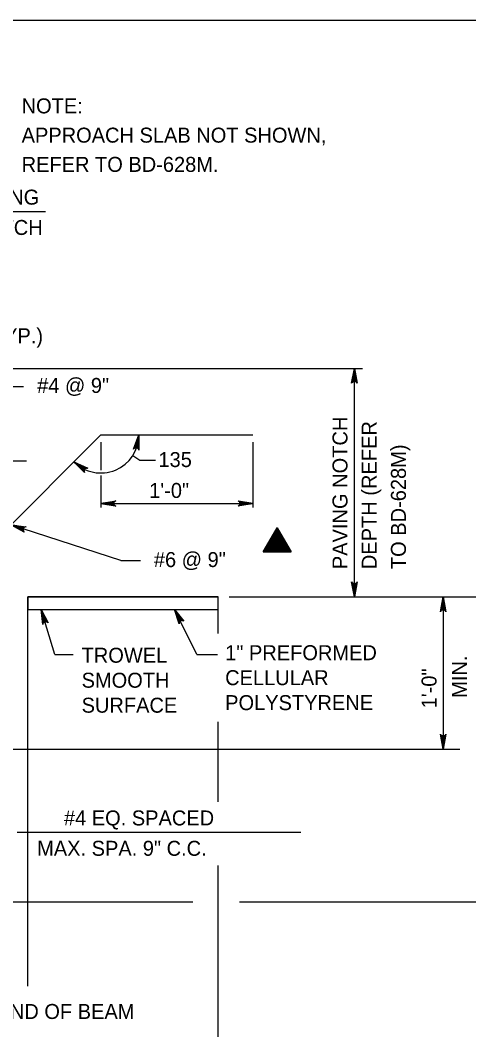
# Model space of a CAD drawing. Extents: x 638653 to 642302, y 298557 to 300414.
# Drawn here: x 640287.7 to 640377.6, y 299527.4 to 299729.5 of the extents above; entities that cross this region are included whole.
import ezdxf

# ---------------------------------------------------------------- set-up
doc = ezdxf.new("R2010")
doc.units = 0
doc.layers.add('1', color=7, linetype='Continuous')

msp = doc.modelspace()

# ---------------------------------------------------------------- linework, layer by layer
at = {"layer": '1'}
for p, q in [((639863.16, 299729.52), (640649.16, 299729.52)), ((640251.13, 299691.25), (640292.75, 299691.25)), ((640275.45, 299659.83), (640356.29, 299659.83)), ((640354.65, 299614.11), (640354.65, 299659.83)), ((640282.86, 299656.2), (640288.33, 299656.2)), ((640240.92, 299583.57), (640303.84, 299646.5)), ((640303.84, 299646.5), (640334.32, 299646.5)), ((640303.84, 299645.08), (640303.84, 299639.47)), ((640334.32, 299645.08), (640334.32, 299631.95)), ((640310.25, 299642.38), (640311.66, 299641.48)), ((640265.67, 299641.32), (640288.96, 299641.32)), ((640311.66, 299641.48), (640314.81, 299641.48)), ((640303.84, 299638.36), (640303.84, 299631.95)), ((640303.84, 299632.78), (640334.32, 299632.78)), ((640307.83, 299621.35), (640285.84, 299628.5)), ((640339.18, 299624.69), (640339.18, 299624.69)), ((640307.83, 299621.35), (640311.8, 299621.35)), ((640289.23, 299536.15), (640289.23, 299614.11)), ((640289.23, 299614.11), (640327.33, 299614.11)), ((640327.33, 299606.73), (640327.33, 299614.11)), ((640329.54, 299614.11), (640386.72, 299614.11)), ((640372.44, 299614.11), (640372.44, 299583.63)), ((640289.23, 299611.57), (640327.33, 299611.57)), ((640294.61, 299602.54), (640291.86, 299611.57)), ((640323.1, 299602.56), (640318.59, 299611.57)), ((640294.61, 299602.54), (640298.3, 299602.54)), ((640323.1, 299602.56), (640327.24, 299602.56)), ((640327.33, 299573.06), (640327.33, 299589.09)), ((640258.7, 299583.63), (640375.77, 299583.63)), ((640287.05, 299566.99), (640343.95, 299566.99)), ((640327.33, 299518.76), (640327.33, 299560.28)), ((640276.15, 299553.07), (640322.31, 299553.07)), ((640331.65, 299553.07), (640386.72, 299553.07))]:
    msp.add_line(p, q, dxfattribs=at)
for points in [[(640354.65, 299659.83), (640355.21, 299656.84), (640355.05, 299657.07), (640354.85, 299657.19), (640354.65, 299657.23), (640354.45, 299657.19), (640354.25, 299657.07), (640354.09, 299656.84), (640354.65, 299659.83), (640354.25, 299657.07), (640354.45, 299657.19), (640354.65, 299659.83), (640354.65, 299657.23), (640354.85, 299657.19), (640354.65, 299659.83), (640355.05, 299657.07)], [(640311.46, 299646.5), (640311.49, 299643.46), (640311.43, 299643.59), (640311.37, 299643.71), (640311.29, 299643.79), (640311.2, 299643.87), (640311.1, 299643.9), (640311.01, 299643.93), (640310.91, 299643.94), (640310.8, 299643.94), (640310.7, 299643.89), (640310.59, 299643.85), (640310.49, 299643.75), (640310.39, 299643.65), (640311.46, 299646.5), (640310.49, 299643.75), (640310.59, 299643.85), (640311.46, 299646.5), (640310.7, 299643.89), (640310.8, 299643.94), (640311.46, 299646.5), (640310.91, 299643.94), (640311.01, 299643.93), (640311.46, 299646.5), (640311.1, 299643.9), (640311.2, 299643.87), (640311.46, 299646.5), (640311.29, 299643.79), (640311.37, 299643.71), (640311.46, 299646.5), (640311.43, 299643.59)], [(640298.45, 299641.11), (640301.22, 299639.87), (640301.08, 299639.87), (640300.94, 299639.87), (640300.84, 299639.82), (640300.73, 299639.78), (640300.66, 299639.7), (640300.59, 299639.63), (640300.55, 299639.54), (640300.5, 299639.45), (640300.5, 299639.33), (640300.49, 299639.21), (640300.54, 299639.08), (640300.59, 299638.95), (640298.45, 299641.11), (640300.54, 299639.08), (640300.49, 299639.21), (640298.45, 299641.11), (640300.5, 299639.33), (640300.5, 299639.45), (640298.45, 299641.11), (640300.55, 299639.54), (640300.59, 299639.63), (640298.45, 299641.11), (640300.66, 299639.7), (640300.73, 299639.78), (640298.45, 299641.11), (640300.84, 299639.82), (640300.94, 299639.87), (640298.45, 299641.11), (640301.08, 299639.87)], [(640303.84, 299632.78), (640306.82, 299633.34), (640306.71, 299633.26), (640306.59, 299633.18), (640306.53, 299633.08), (640306.47, 299632.98), (640306.46, 299632.88), (640306.44, 299632.78), (640306.46, 299632.68), (640306.47, 299632.58), (640306.53, 299632.48), (640306.59, 299632.38), (640306.71, 299632.3), (640306.82, 299632.23), (640303.84, 299632.78), (640306.71, 299632.3), (640306.59, 299632.38), (640303.84, 299632.78), (640306.53, 299632.48), (640306.47, 299632.58), (640303.84, 299632.78), (640306.46, 299632.68), (640306.44, 299632.78), (640303.84, 299632.78), (640306.46, 299632.88), (640306.47, 299632.98), (640303.84, 299632.78), (640306.53, 299633.08), (640306.59, 299633.18), (640303.84, 299632.78), (640306.71, 299633.26)], [(640334.32, 299632.78), (640331.34, 299632.23), (640331.45, 299632.3), (640331.57, 299632.38), (640331.62, 299632.48), (640331.68, 299632.58), (640331.7, 299632.68), (640331.72, 299632.78), (640331.7, 299632.88), (640331.68, 299632.98), (640331.62, 299633.08), (640331.57, 299633.18), (640331.45, 299633.26), (640331.34, 299633.34), (640334.32, 299632.78), (640331.45, 299633.26), (640331.57, 299633.18), (640334.32, 299632.78), (640331.62, 299633.08), (640331.68, 299632.98), (640334.32, 299632.78), (640331.7, 299632.88), (640331.72, 299632.78), (640334.32, 299632.78), (640331.7, 299632.68), (640331.68, 299632.58), (640334.32, 299632.78), (640331.62, 299632.48), (640331.57, 299632.38), (640334.32, 299632.78), (640331.45, 299632.3)], [(640285.84, 299628.5), (640288.85, 299628.13), (640288.72, 299628.08), (640288.58, 299628.04), (640288.5, 299627.97), (640288.41, 299627.89), (640288.36, 299627.8), (640288.32, 299627.71), (640288.3, 299627.61), (640288.29, 299627.51), (640288.32, 299627.39), (640288.34, 299627.28), (640288.43, 299627.17), (640288.51, 299627.06), (640285.84, 299628.5), (640288.43, 299627.17), (640288.34, 299627.28), (640285.84, 299628.5), (640288.32, 299627.39), (640288.29, 299627.51), (640285.84, 299628.5), (640288.3, 299627.61), (640288.32, 299627.71), (640285.84, 299628.5), (640288.36, 299627.8), (640288.41, 299627.89), (640285.84, 299628.5), (640288.5, 299627.97), (640288.58, 299628.04), (640285.84, 299628.5), (640288.72, 299628.08)], [(640336.39, 299623.08), (640341.97, 299623.08), (640339.18, 299627.91), (640336.39, 299623.08)], [(640336.39, 299623.08), (640339.18, 299627.91), (640341.97, 299623.08), (640336.39, 299623.08), (640339.17, 299627.77), (640341.88, 299623.15), (640336.5, 299623.14), (640339.18, 299627.63), (640341.76, 299623.22), (640336.63, 299623.2), (640339.19, 299627.48), (640341.64, 299623.31), (640336.75, 299623.27), (640339.18, 299627.34), (640341.52, 299623.37), (640336.88, 299623.36), (640339.19, 299627.17), (640341.38, 299623.44), (640337.03, 299623.44), (640339.18, 299627), (640341.25, 299623.52), (640337.16, 299623.51), (640339.17, 299626.83), (640341.11, 299623.61), (640337.3, 299623.59), (640339.17, 299626.67), (640340.96, 299623.69), (640337.43, 299623.67), (640339.19, 299626.52), (640340.79, 299623.77), (640337.57, 299623.75), (640339.19, 299626.35), (640340.62, 299623.88), (640337.72, 299623.83), (640339.19, 299626.17), (640340.48, 299623.98), (640337.87, 299623.91), (640339.19, 299626), (640340.33, 299624.06), (640338.04, 299623.99), (640339.19, 299625.84), (640340.19, 299624.14), (640338.2, 299624.07), (640339.19, 299625.66), (640340.03, 299624.23), (640338.37, 299624.16), (640339.19, 299625.5), (640339.86, 299624.32), (640338.5, 299624.24), (640339.18, 299625.33), (640339.71, 299624.41), (640338.66, 299624.31), (640339.18, 299625.18), (640339.57, 299624.46), (640338.79, 299624.39), (640339.18, 299625.02), (640339.45, 299624.54), (640338.92, 299624.46), (640339.19, 299624.86), (640339.34, 299624.6), (640339.07, 299624.56), (640339.18, 299624.69), (640341.95, 299623.1), (640339.18, 299624.69), (640339.18, 299627.88), (640339.19, 299624.68), (640336.4, 299623.09)], [(640354.65, 299614.11), (640354.09, 299617.09), (640354.25, 299616.86), (640354.45, 299616.74), (640354.65, 299616.71), (640354.85, 299616.74), (640355.05, 299616.86), (640355.21, 299617.09), (640354.65, 299614.11), (640355.05, 299616.86), (640354.85, 299616.74), (640354.65, 299614.11), (640354.65, 299616.71), (640354.45, 299616.74), (640354.65, 299614.11), (640354.25, 299616.86)], [(640372.44, 299614.11), (640373, 299611.12), (640372.92, 299611.24), (640372.84, 299611.35), (640372.74, 299611.41), (640372.64, 299611.47), (640372.54, 299611.49), (640372.44, 299611.51), (640372.34, 299611.49), (640372.24, 299611.47), (640372.14, 299611.41), (640372.04, 299611.35), (640371.96, 299611.24), (640371.88, 299611.12), (640372.44, 299614.11), (640371.96, 299611.24), (640372.04, 299611.35), (640372.44, 299614.11), (640372.14, 299611.41), (640372.24, 299611.47), (640372.44, 299614.11), (640372.34, 299611.49), (640372.44, 299611.51), (640372.44, 299614.11), (640372.54, 299611.49), (640372.64, 299611.47), (640372.44, 299614.11), (640372.74, 299611.41), (640372.84, 299611.35), (640372.44, 299614.11), (640372.92, 299611.24)], [(640291.86, 299611.57), (640293.26, 299608.88), (640293.15, 299608.96), (640293.04, 299609.05), (640292.93, 299609.08), (640292.82, 299609.11), (640292.72, 299609.09), (640292.62, 299609.08), (640292.53, 299609.04), (640292.44, 299608.99), (640292.36, 299608.9), (640292.28, 299608.82), (640292.24, 299608.69), (640292.19, 299608.55), (640291.86, 299611.57), (640292.24, 299608.69), (640292.28, 299608.82), (640291.86, 299611.57), (640292.36, 299608.9), (640292.44, 299608.99), (640291.86, 299611.57), (640292.53, 299609.04), (640292.62, 299609.08), (640291.86, 299611.57), (640292.72, 299609.09), (640292.82, 299609.11), (640291.86, 299611.57), (640292.93, 299609.08), (640293.04, 299609.05), (640291.86, 299611.57), (640293.15, 299608.96)], [(640318.59, 299611.57), (640320.5, 299609.21), (640320.37, 299609.27), (640320.25, 299609.34), (640320.13, 299609.34), (640320.02, 299609.34), (640319.92, 299609.31), (640319.82, 299609.28), (640319.74, 299609.22), (640319.66, 299609.15), (640319.6, 299609.06), (640319.54, 299608.96), (640319.53, 299608.82), (640319.51, 299608.68), (640318.59, 299611.57), (640319.53, 299608.82), (640319.54, 299608.96), (640318.59, 299611.57), (640319.6, 299609.06), (640319.66, 299609.15), (640318.59, 299611.57), (640319.74, 299609.22), (640319.82, 299609.28), (640318.59, 299611.57), (640319.92, 299609.31), (640320.02, 299609.34), (640318.59, 299611.57), (640320.13, 299609.34), (640320.25, 299609.34), (640318.59, 299611.57), (640320.37, 299609.27)], [(640372.44, 299583.63), (640371.88, 299586.61), (640371.96, 299586.49), (640372.04, 299586.38), (640372.14, 299586.32), (640372.24, 299586.26), (640372.34, 299586.24), (640372.44, 299586.23), (640372.54, 299586.24), (640372.64, 299586.26), (640372.74, 299586.32), (640372.84, 299586.38), (640372.92, 299586.49), (640373, 299586.61), (640372.44, 299583.63), (640372.92, 299586.49), (640372.84, 299586.38), (640372.44, 299583.63), (640372.74, 299586.32), (640372.64, 299586.26), (640372.44, 299583.63), (640372.54, 299586.24), (640372.44, 299586.23), (640372.44, 299583.63), (640372.34, 299586.24), (640372.24, 299586.26), (640372.44, 299583.63), (640372.14, 299586.32), (640372.04, 299586.38), (640372.44, 299583.63), (640371.96, 299586.49)]]:
    msp.add_lwpolyline(points, dxfattribs=at)
msp.add_lwpolyline([(640289.23, 299611.57), (640327.33, 299611.57), (640327.33, 299614.11), (640289.23, 299614.11)], close=True, dxfattribs=at)
msp.add_arc((640303.84, 299646.5), 7.62, 225, 0, dxfattribs=at)

# ---------------------------------------------------------------- texts
for s, p in [('NOTE:', (640287.97, 299710.87)), ('APPROACH SLAB NOT SHOWN,', (640287.97, 299705.01)), ('REFER TO BD-628M.', (640287.97, 299699.16)), ('PAVING', (640276.35, 299692.6)), ('NOTCH', (640277.93, 299686.53)), ('TO SKEW (TYP.)', (640261.06, 299664.85)), ('#4 @ 9"', (640291.08, 299654.91)), ('135', (640315.39, 299640.07)), ('1\'-0"', (640313.54, 299633.89)), ('#6 @ 9"', (640314.47, 299620.05)), ('TROWEL', (640299.99, 299600.9)), ('1" PREFORMED', (640328.76, 299601.41)), ('SMOOTH', (640299.99, 299595.9)), ('CELLULAR', (640328.76, 299596.41)), ('SURFACE', (640299.99, 299590.9)), ('POLYSTYRENE', (640328.76, 299591.41)), ('#4 EQ. SPACED', (640296.45, 299568.33)), ('MAX. SPA. 9" C.C.', (640291.08, 299562.25)), ('END OF BEAM', (640282.94, 299529.59))]:
    msp.add_text(s, height=3, dxfattribs=at).set_placement(p)
for s, p in [('PAVING NOTCH', (640353.27, 299619.63)), ('DEPTH (REFER', (640359.12, 299619.63)), ('TO BD-628M)', (640364.98, 299619.63)), ('MIN.', (640377.19, 299593.87)), ('1\'-0"', (640371.12, 299591.77))]:
    msp.add_text(s, height=3, rotation=90, dxfattribs=at).set_placement(p)

doc.saveas('drawing.dxf')
